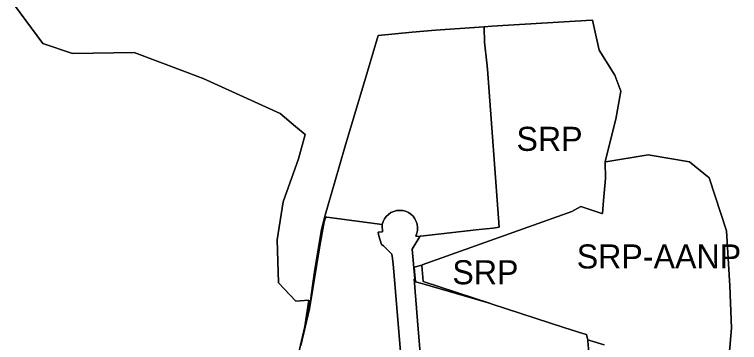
# Model space of a CAD drawing. Extents: x 598968 to 613553, y 4409678 to 4430833.
# Drawn here: x 601840 to 602201.6, y 4410427.8 to 4410591.4 of the extents above; entities that cross this region are included whole.
import ezdxf

# ---------------------------------------------------------------- set-up
doc = ezdxf.new("R2010")
doc.units = 0
for name, color, linetype in [('1', 7, 'Continuous'), ('Sòl Rústic Protegit', 7, 'Continuous'), ('Sòl Rústic Protegit - Alt Nivell de Protecció', 7, 'Continuous'), ('ZONA 4. CASES UNIFAMILIRAS AÏLLADES EN PARCEL.LES', 7, 'Continuous'), ('ZONA 7. CONJUNTS AMB ORDENACIONS ESPECÍFIQUES', 7, 'Continuous')]:
    doc.layers.add(name, color=color, linetype=linetype)

msp = doc.modelspace()

# ---------------------------------------------------------------- linework, layer by layer
at = {"layer": '1'}
for points in [[(602047.998, 4410354.6641), (602041.0444, 4410438.5721), (602039.3786, 4410459.5911), (602039.6024, 4410459.5184), (602038.3159, 4410474.3162), (602042.2145, 4410480.7519), (602040.128, 4410480.8731), (602040.6828, 4410482.2785), (602040.9921, 4410483.7575), (602041.0471, 4410485.2673), (602040.8462, 4410486.7649), (602040.395, 4410488.2069), (602039.7067, 4410489.552), (602038.801, 4410490.7614), (602037.704, 4410491.8004), (602036.4471, 4410492.639), (602035.0666, 4410493.2532), (602033.6022, 4410493.6253), (602032.096, 4410493.7447), (602030.5913, 4410493.6077), (602029.1313, 4410493.2184), (602027.7581, 4410492.5881), (602026.5112, 4410491.7348), (602025.4264, 4410490.683), (602024.5349, 4410489.4631), (602023.8623, 4410488.11), (602023.4284, 4410486.6638), (602023.4461, 4410486.662), (602023.2981, 4410486.3628), (602023.5081, 4410483.0129), (602021.3781, 4410482.7828), (602021.7681, 4410481.0029), (602023.0981, 4410476.6629), (602024.0281, 4410476.0529), (602028.1981, 4410471.953), (602028.5681, 4410469.713), (602028.8581, 4410466.8731), (602029.1781, 4410463.0931), (602041.2681, 4410317.7143)], [(602134.0383, 4410426.6737), (602127.0042, 4410428.8253), (602126.5343, 4410428.969), (602125.8752, 4410429.0982), (602125.9684, 4410428.6512), (602126.6072, 4410420.5945)]]:
    msp.add_lwpolyline(points, dxfattribs=at)
at = {"layer": 'Sòl Rústic Protegit'}
msp.add_lwpolyline([(601839.9927, 4410596.0098), (601854.1177, 4410577.0098), (601868.9927, 4410572.0098), (601899.6801, 4410572.5098), (601934.0551, 4410559.5098), (601972.4301, 4410542.0098), (601980.1177, 4410535.5098), (601984.9301, 4410531.5098), (601981.5551, 4410519.5098), (601974.0551, 4410498.0098), (601970.9301, 4410479.0098), (601971.7427, 4410457.5098), (601980.3677, 4410448.5098), (601986.8051, 4410449.0098), (601984.7401, 4410435.7929), (601986.8056, 4410445.005), (601987.8105, 4410449.4871), (601987.7568, 4410449.9204), (601988.6288, 4410456.139), (601989.4386, 4410461.8985), (601989.8082, 4410464.2127), (601993.0851, 4410484.1064), (601994.9798, 4410491.3039), (601999.7428, 4410507.9138), (602004.7165, 4410525.2646), (602016.0265, 4410563.045), (602021.4161, 4410581.034), (602038.3155, 4410582.5708), (602049.9166, 4410583.6258), (602074.1821, 4410585.3606), (602074.1825, 4410585.3416), (602077.9891, 4410585.6838), (602127.9897, 4410588.684), (602127.9971, 4410588.6518), (602128.1871, 4410588.6632), (602131.6245, 4410573.6634), (602139.4369, 4410561.1634), (602142.3745, 4410553.1636), (602139.9371, 4410539.1636), (602134.6245, 4410518.1638), (602134.6257, 4410517.9956), (602134.8677, 4410518.0098), (602155.9927, 4410521.5098), (602176.6177, 4410518.0098), (602186.4927, 4410510.0098), (602195.1177, 4410483.5098), (602196.8051, 4410456.0098), (602197.6177, 4410435.0098), (602195.1897, 4410407.969)], dxfattribs=at)
for points in [[(602134.6257, 4410517.9956), (602134.6245, 4410518.1638), (602139.9371, 4410539.1636), (602142.3745, 4410553.1636), (602139.4369, 4410561.1634), (602131.6245, 4410573.6634), (602128.1871, 4410588.6632), (602127.9971, 4410588.6518), (602127.9897, 4410588.684), (602077.9891, 4410585.6838), (602074.1825, 4410585.3416), (602074.1888, 4410585.0214), (602074.3351, 4410577.5954), (602075.5354, 4410567.3251), (602075.9621, 4410564.0819), (602081.7874, 4410485.2785), (602078.6799, 4410484.9329), (602071.8001, 4410484.1677), (602044.0329, 4410481.0794), (602042.2959, 4410480.8862), (602042.2145, 4410480.7519), (602038.3159, 4410474.3162), (602039.6024, 4410459.5184), (602039.7165, 4410458.206), (602039.9516, 4410458.1375), (602039.5121, 4410463.1888), (602039.3151, 4410465.4528), (602043.1517, 4410466.448), (602043.2835, 4410466.495), (602043.2973, 4410466.5), (602117.9997, 4410493.1638), (602122.5107, 4410495.6356), (602132.9893, 4410492.1838), (602132.9935, 4410492.2278), (602133.1871, 4410492.164), (602133.8121, 4410498.664), (602134.6871, 4410509.6638)], [(602077.4009, 4410447.2328), (602043.8183, 4410458.2138), (602043.1705, 4410466.215), (602043.2973, 4410466.5), (602043.2835, 4410466.495), (602043.1517, 4410466.448), (602039.3151, 4410465.4528), (602039.5121, 4410463.1888), (602039.9516, 4410458.1375), (602043.1701, 4410457.2004)]]:
    msp.add_lwpolyline(points, close=True, dxfattribs=at)
at = {"layer": 'Sòl Rústic Protegit - Alt Nivell de Protecció'}
for points in [[(601981.5264, 4410421.4597), (601984.7401, 4410435.7929), (601986.8051, 4410449.0098), (601980.3677, 4410448.5098), (601971.7427, 4410457.5098), (601970.9301, 4410479.0098), (601974.0551, 4410498.0098), (601981.5551, 4410519.5098), (601984.9301, 4410531.5098), (601980.1177, 4410535.5098), (601972.4301, 4410542.0098), (601934.0551, 4410559.5098), (601899.6801, 4410572.5098), (601868.9927, 4410572.0098), (601854.1177, 4410577.0098), (601839.9927, 4410596.0098)], [(602195.1897, 4410407.969), (602197.6177, 4410435.0098), (602196.8051, 4410456.0098), (602195.1177, 4410483.5098), (602186.4927, 4410510.0098), (602176.6177, 4410518.0098), (602155.9927, 4410521.5098), (602134.8677, 4410518.0098), (602134.6257, 4410517.9956), (602134.6871, 4410509.6638), (602133.8121, 4410498.664), (602133.1871, 4410492.164), (602132.9935, 4410492.2278), (602132.9893, 4410492.1838), (602122.5107, 4410495.6356), (602117.9997, 4410493.1638), (602043.2973, 4410466.5), (602043.1705, 4410466.215), (602043.8183, 4410458.2138), (602077.4009, 4410447.2328), (602077.6916, 4410447.1482), (602114.4316, 4410435.216), (602123.4273, 4410432.2944), (602123.4977, 4410432.2772), (602125.3046, 4410431.8345), (602125.3366, 4410431.6811), (602125.8752, 4410429.0982), (602126.5343, 4410428.969), (602127.0042, 4410428.8253), (602134.0383, 4410426.6737)]]:
    msp.add_lwpolyline(points, dxfattribs=at)
at = {"layer": 'ZONA 4. CASES UNIFAMILIRAS AÏLLADES EN PARCEL.LES'}
for points in [[(602041.2681, 4410317.7143), (602029.1781, 4410463.0931), (602028.8581, 4410466.8731), (602028.5681, 4410469.713), (602028.1981, 4410471.953), (602024.0281, 4410476.0529), (602023.0981, 4410476.6629), (602021.7681, 4410481.0029), (602021.3781, 4410482.7828), (602023.5081, 4410483.0129), (602023.2981, 4410486.3628), (602023.4461, 4410486.662), (602023.4284, 4410486.6638), (601995.7432, 4410490.3142), (601995.2312, 4410490.3817), (601994.4384, 4410487.9625), (601992.2883, 4410476.1226), (601987.1384, 4410444.6427), (601982.869, 4410426.3771)], [(602126.6072, 4410420.5945), (602125.9684, 4410428.6512), (602125.8752, 4410429.0982), (602125.3366, 4410431.6811), (602125.3046, 4410431.8345), (602123.4977, 4410432.2772), (602123.4273, 4410432.2944), (602114.4316, 4410435.216), (602077.6916, 4410447.1482), (602077.4009, 4410447.2328), (602043.1701, 4410457.2004), (602039.9516, 4410458.1375), (602039.7165, 4410458.206), (602039.6024, 4410459.5184), (602039.3786, 4410459.5911), (602041.0444, 4410438.5721), (602047.998, 4410354.6641)]]:
    msp.add_lwpolyline(points, dxfattribs=at)
at = {"layer": 'ZONA 7. CONJUNTS AMB ORDENACIONS ESPECÍFIQUES'}
msp.add_lwpolyline([(601982.869, 4410426.3771), (601987.1384, 4410444.6427), (601992.2883, 4410476.1226), (601994.4384, 4410487.9625), (601995.2312, 4410490.3817), (601995.7432, 4410490.3142), (602023.4284, 4410486.6638), (602023.8623, 4410488.11), (602024.5349, 4410489.4631), (602025.4264, 4410490.683), (602026.5112, 4410491.7348), (602027.7581, 4410492.5881), (602029.1313, 4410493.2184), (602030.5913, 4410493.6077), (602032.096, 4410493.7447), (602033.6022, 4410493.6253), (602035.0666, 4410493.2532), (602036.4471, 4410492.639), (602037.704, 4410491.8004), (602038.801, 4410490.7614), (602039.7067, 4410489.552), (602040.395, 4410488.2069), (602040.8462, 4410486.7649), (602041.0471, 4410485.2673), (602040.9921, 4410483.7575), (602040.6828, 4410482.2785), (602040.128, 4410480.8731), (602042.2145, 4410480.7519), (602042.2959, 4410480.8862), (602044.0329, 4410481.0794), (602071.8001, 4410484.1677), (602078.6799, 4410484.9329), (602081.7874, 4410485.2785), (602075.9621, 4410564.0819), (602075.5354, 4410567.3251), (602074.3351, 4410577.5954), (602074.1888, 4410585.0214), (602074.1825, 4410585.3416), (602074.1821, 4410585.3606), (602049.9166, 4410583.6258), (602038.3155, 4410582.5708), (602021.4161, 4410581.034), (602016.0265, 4410563.045), (602004.7165, 4410525.2646), (601999.7428, 4410507.9138), (601994.9798, 4410491.3039), (601993.0851, 4410484.1064), (601989.8082, 4410464.2127), (601989.4386, 4410461.8985), (601988.6288, 4410456.139), (601987.7568, 4410449.9204), (601987.8105, 4410449.4871), (601986.8056, 4410445.005), (601984.7401, 4410435.7929), (601981.5264, 4410421.4597)], dxfattribs=at)

# ---------------------------------------------------------------- texts
at = {"layer": 'Sòl Rústic Protegit'}
for p in [(602090.3452, 4410523.4108), (602058.358, 4410456.8664)]:
    msp.add_text('SRP', height=12, dxfattribs=at).set_placement(p)
at = {"layer": 'Sòl Rústic Protegit - Alt Nivell de Protecció'}
msp.add_text('SRP-AANP', height=12, dxfattribs=at).set_placement((602120.3941, 4410464.7394))

doc.saveas('drawing.dxf')
